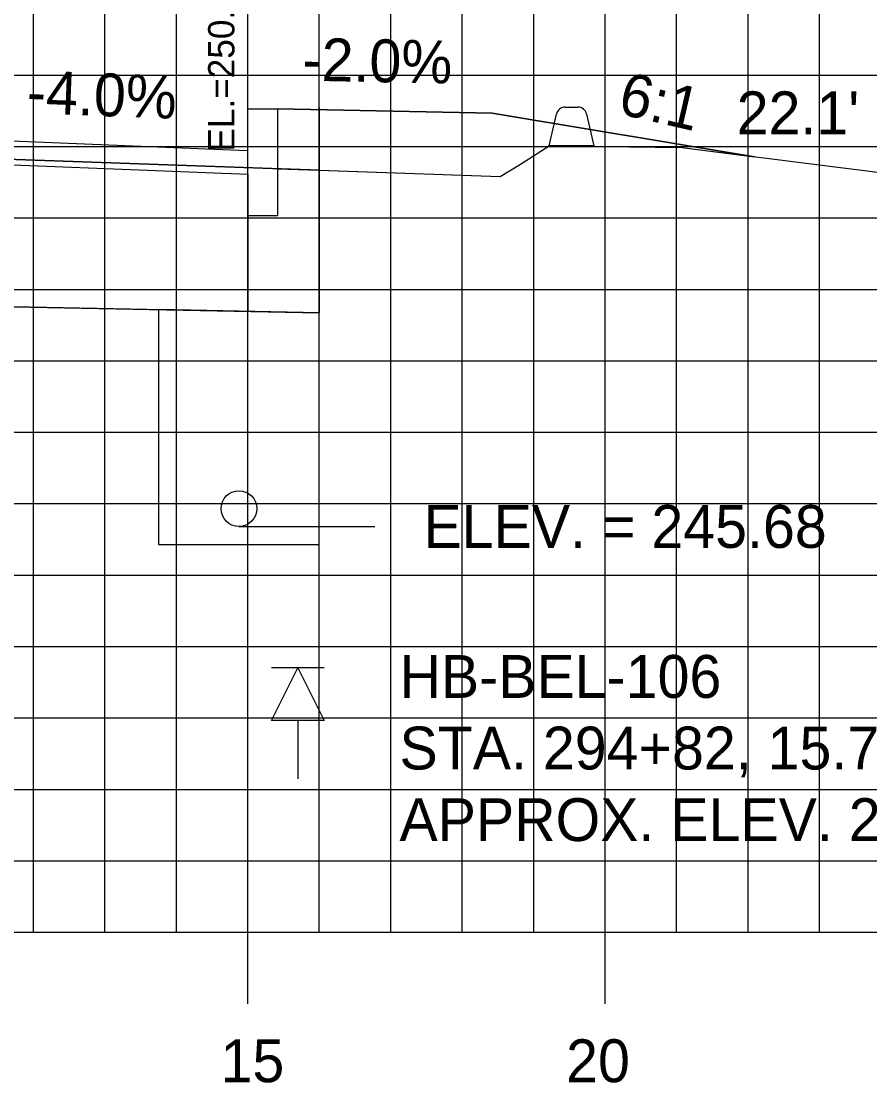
# Model space of a CAD drawing. Extents: x 859352 to 859522, y 366268 to 366378.
# Drawn here: x 859446.96 to 859458.83, y 366335.13 to 366349.99 of the extents above; entities that cross this region are included whole.
import ezdxf

# ---------------------------------------------------------------- set-up
doc = ezdxf.new("R2010")
doc.units = 0
for name, color, linetype in [('ANNOTATION', 7, 'Continuous'), ('D_Curb_Type_1_Rt', 7, 'Continuous'), ('D_Roadway_Edge_Shoulder', 7, 'Continuous'), ('D_Roadway_FinishedGrade', 7, 'Continuous'), ('D_Roadway_SubGrade', 7, 'Continuous'), ('D_Text_Standard', 7, 'Continuous'), ('H_V ANNOTATION', 7, 'Continuous'), ('JUNK COM EXC', 7, 'Continuous'), ('JUNK FILL', 7, 'Continuous'), ('junk strct exc', 7, 'Continuous'), ('MAJOR', 7, 'Continuous'), ('MINOR', 7, 'Continuous'), ('PDRAIN', 7, 'Continuous'), ('ROCKS', 7, 'Continuous'), ('S_Curb_Type_3', 7, 'Continuous'), ('S_Roadway_Centerline', 7, 'Continuous')]:
    doc.layers.add(name, color=color, linetype=linetype)

msp = doc.modelspace()

# ---------------------------------------------------------------- linework, layer by layer
at = {"layer": 'D_Curb_Type_1_Rt'}
msp.add_lwpolyline([(859450.546, 366348.764), (859450.546, 366347.264), (859450.13, 366347.264), (859450.13, 366348.764)], close=True, dxfattribs=at)
at = {"layer": 'D_Roadway_Edge_Shoulder'}
msp.add_lwpolyline([(859420.129, 366348.181), (859424.129, 366348.341), (859435.129, 366348.561), (859446.129, 366348.341), (859450.121, 366348.181)], dxfattribs=at)
at = {"layer": 'D_Roadway_FinishedGrade'}
msp.add_line((859453.546, 366348.704), (859457.217, 366348.093), dxfattribs=at)
msp.add_lwpolyline([(859450.546, 366348.764), (859453.546, 366348.704)], dxfattribs=at)
at = {"layer": 'D_Roadway_SubGrade'}
msp.add_lwpolyline([(859451.129, 366348.776), (859451.129, 366345.907), (859450.129, 366345.927)], dxfattribs=at)
msp.add_lwpolyline([(859446.129, 366348.007), (859450.129, 366347.847), (859450.129, 366345.927), (859446.129, 366346.007)], close=True, dxfattribs=at)
at = {"layer": 'D_Text_Standard'}
msp.add_lwpolyline([(859450.004, 366342.916), (859451.227, 366342.916), (859451.907, 366342.916)], dxfattribs=at)
at = {"layer": 'JUNK COM EXC'}
msp.add_lwpolyline([(859451.129, 366347.905), (859445.818, 366348.091), (859445.715, 366348.095), (859445.604, 366348.098), (859436.054, 366348.372), (859425.319, 366348.22), (859424.742, 366348.213), (859423.783, 366348.18), (859421.575, 366348.105), (859420.543, 366348.079), (859419.973, 366348.478), (859419.901, 366348.53), (859418.627, 366348.55), (859417.106, 366348.582), (859415.438, 366348.625), (859415.124, 366348.545), (859415.124, 366347.689), (859416.644, 366347.659), (859416.644, 366345.858), (859419.129, 366345.907), (859424.129, 366346.007), (859435.129, 366346.236), (859446.129, 366346.007), (859451.129, 366345.907)], close=True, dxfattribs=at)
at = {"layer": 'JUNK FILL'}
msp.add_lwpolyline([(859450.546, 366347.925), (859451.129, 366347.905), (859453.662, 366347.816), (859453.944, 366347.99), (859454.346, 366348.245), (859456.203, 366348.22), (859457.217, 366348.093), (859453.546, 366348.704), (859450.546, 366348.764)], close=True, dxfattribs=at)
at = {"layer": 'junk strct exc'}
msp.add_lwpolyline([(859448.879, 366345.952), (859448.879, 366342.666), (859451.129, 366342.666), (859451.129, 366345.907)], close=True, dxfattribs=at)
at = {"layer": 'MAJOR'}
for p, q in [((859450.129, 366337.236), (859450.129, 366357.236)), ((859455.129, 366337.236), (859455.129, 366357.236)), ((859365.129, 366347.236), (859505.129, 366347.236)), ((859365.129, 366342.236), (859505.129, 366342.236)), ((859365.129, 366337.236), (859505.129, 366337.236)), ((859365.129, 366337.236), (859505.129, 366337.236)), ((859450.129, 366336.234), (859450.129, 366337.236)), ((859455.129, 366336.234), (859455.129, 366337.236))]:
    msp.add_line(p, q, dxfattribs=at)
at = {"layer": 'MINOR'}
for p, q in [((859447.129, 366337.236), (859447.129, 366357.236)), ((859448.129, 366337.236), (859448.129, 366357.236)), ((859449.129, 366337.236), (859449.129, 366357.236)), ((859451.129, 366337.236), (859451.129, 366357.236)), ((859452.129, 366337.236), (859452.129, 366357.236)), ((859453.129, 366337.236), (859453.129, 366357.236)), ((859454.129, 366337.236), (859454.129, 366357.236)), ((859456.129, 366337.236), (859456.129, 366357.236)), ((859457.129, 366337.236), (859457.129, 366357.236)), ((859458.129, 366337.236), (859458.129, 366357.236)), ((859365.129, 366349.236), (859505.129, 366349.236)), ((859365.129, 366348.236), (859505.129, 366348.236)), ((859365.129, 366346.236), (859505.129, 366346.236)), ((859365.129, 366345.236), (859505.129, 366345.236)), ((859365.129, 366344.236), (859505.129, 366344.236)), ((859365.129, 366343.236), (859505.129, 366343.236)), ((859365.129, 366341.236), (859505.129, 366341.236)), ((859365.129, 366340.236), (859505.129, 366340.236)), ((859365.129, 366339.236), (859505.129, 366339.236)), ((859365.129, 366339.236), (859505.129, 366339.236)), ((859365.129, 366338.236), (859505.129, 366338.236))]:
    msp.add_line(p, q, dxfattribs=at)
at = {"layer": 'PDRAIN'}
msp.add_lwpolyline([(859448.879, 366345.952), (859448.879, 366342.666), (859451.129, 366342.666), (859451.129, 366345.907)], dxfattribs=at)
msp.add_circle((859450.004, 366343.166), 0.25, dxfattribs=at)
at = {"layer": 'ROCKS'}
for p, q in [((859451.198, 366340.936), (859450.46, 366340.936)), ((859450.829, 366340.198), (859450.829, 366339.384))]:
    msp.add_line(p, q, dxfattribs=at)
msp.add_lwpolyline([(859450.829, 366340.936), (859451.198, 366340.198), (859450.46, 366340.198)], close=True, dxfattribs=at)
at = {"layer": 'S_Curb_Type_3'}
for points in [[(859454.868, 366348.69), (859454.971, 366348.245), (859454.346, 366348.245), (859454.449, 366348.69)], [(859454.57, 366348.787), (859454.747, 366348.787)]]:
    msp.add_lwpolyline(points, dxfattribs=at)
for centre, start, end in [((859454.57, 366348.662), 90, 167.0054), ((859454.747, 366348.662), 12.9946, 90)]:
    msp.add_arc(centre, 0.125, start, end, dxfattribs=at)
at = {"layer": 'S_Roadway_Centerline'}
msp.add_lwpolyline([(859445.818, 366348.091), (859453.662, 366347.816), (859453.944, 366347.99), (859454.346, 366348.245), (859456.203, 366348.22), (859462.014, 366347.49), (859464.97, 366347.207), (859466.549, 366347.136), (859468.064, 366346.907), (859475.033, 366346.391), (859476.741, 366345.729)], dxfattribs=at)

# ---------------------------------------------------------------- texts
at = {"layer": 'ANNOTATION'}
for s, rotation, p in [('-2.0%', 358.8544, (859450.889, 366349.158)), ('-4.0%', 357.7092, (859447.028, 366348.705)), ('6:1', 346.9679, (859455.289, 366348.701))]:
    msp.add_text(s, height=0.6, rotation=rotation, dxfattribs=at).set_placement(p)
at = {"layer": 'D_Text_Standard'}
msp.add_text(' EL.=250.94', height=0.36848, rotation=90, dxfattribs=at).set_placement((859449.941, 366348.026))
for s, p in [("22.1'", (859456.97, 366348.407)), ('ELEV. = 245.68', (859452.587, 366342.616))]:
    msp.add_text(s, height=0.6, dxfattribs=at).set_placement(p)
at = {"layer": 'H_V ANNOTATION'}
for s, p in [('15', (859449.747, 366335.136)), ('20', (859454.583, 366335.136))]:
    msp.add_text(s, height=0.6, dxfattribs=at).set_placement(p)
at = {"layer": 'ROCKS'}
for s, p in [('HB-BEL-106', (859452.251, 366340.516)), ("STA. 294+82, 15.7'RT", (859452.251, 366339.514)), ("APPROX. ELEV. 243.7'", (859452.251, 366338.512))]:
    msp.add_text(s, height=0.6, dxfattribs=at).set_placement(p)

doc.saveas('drawing.dxf')
